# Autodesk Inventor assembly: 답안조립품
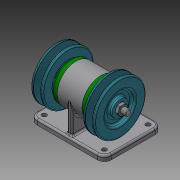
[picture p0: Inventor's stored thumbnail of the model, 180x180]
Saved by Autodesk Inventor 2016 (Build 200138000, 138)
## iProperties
Created: 2019-09
Part Number: 답안조립품
Material: 일반
Document SubType Name: Assembly
Designer: Administrator
Author: Administrator
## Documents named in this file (12)
- C:\Users\Administrator\Desktop\490904V1027\답안조립품.iam
- C:\Users\Administrator\Desktop\490904V1027\본체.ipt
- C:\Users\Administrator\Desktop\490904V1027\축.ipt
- C:\Users\Administrator\Desktop\490904V1027\베어링 6004.ipt
- C:\Users\Administrator\Desktop\490904V1027\커버.ipt
- C:\Users\Administrator\Desktop\490904V1027\오일 실 17 30 5.ipt
- C:\Users\Administrator\Desktop\490904V1027\키 5 x 5 x 12.ipt
- C:\Users\Administrator\Desktop\490904V1027\V-벨트풀리.ipt
- C:\Users\Administrator\Desktop\490904V1027\너트 M10x1.ipt
- C:\Users\Administrator\Desktop\490904V1027\볼트 M4.ipt
- C:\Users\Administrator\Desktop\490904V1027\커버_MIR.ipt
- C:\Users\Administrator\Desktop\490904V1027\V-벨트풀리_MIR.ipt
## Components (2 placed, 2 different names)
1. V-벨트풀리:1
2. V-벨트풀리_MIR:1
